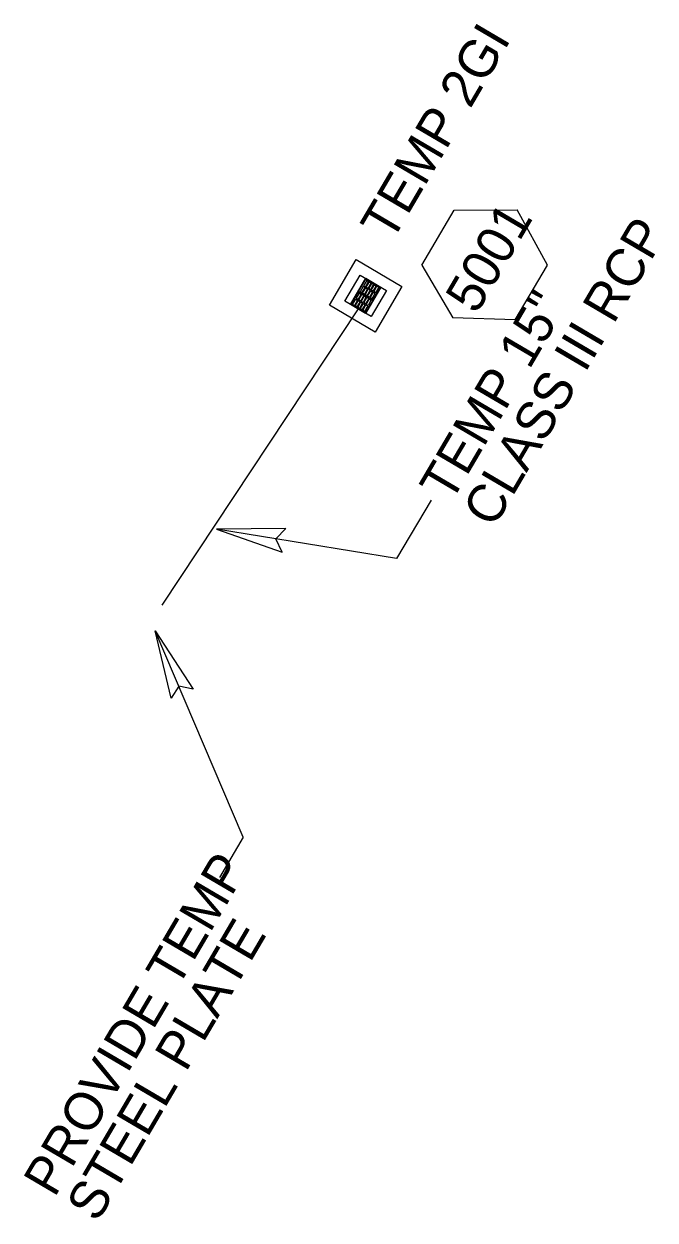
# Model space of a CAD drawing. Extents: x 2214978 to 2238755, y 984122 to 1016255.
# Drawn here: x 2229899 to 2229982.3, y 1001240.8 to 1001398.5 of the extents above; entities that cross this region are included whole.
import ezdxf

# ---------------------------------------------------------------- set-up
doc = ezdxf.new("R2010")
doc.units = 0
for name, color, linetype in [('Prop Drainage Structure Box Number Symbol CELL', 7, 'Continuous'), ('Prop Drainage Structure Drop Inlet Grate 2 Wide Slots and Sag Grates 840 22 CELL', 7, 'Continuous'), ('Prop Drainage Structure Drop Inlet Grate 2 Wide Slots and Sag Grates 840 22 Label', 7, 'Continuous'), ('Prop Drainage Structure Pipe RCP 15in Class III', 7, 'Continuous'), ('Prop Drainage Structure Plot Symbol 20 Scale', 7, 'Continuous'), ('Prop Drainage Structure Plot Symbol 50 Scale', 7, 'Continuous'), ('Prop Plan Preparation Drainage Notes Label', 7, 'Continuous')]:
    doc.layers.add(name, color=color, linetype=linetype)

msp = doc.modelspace()

# ---------------------------------------------------------------- linework, layer by layer
at = {"layer": 'Prop Drainage Structure Box Number Symbol CELL'}
for p, q in [((2229951.54, 1001366.72), (2229955.79, 1001373.96)), ((2229955.79, 1001373.96), (2229964.11, 1001374.02)), ((2229968.1, 1001366.73), (2229964.11, 1001374.02)), ((2229951.54, 1001366.72), (2229955.64, 1001359.76)), ((2229963.84, 1001359.49), (2229968.1, 1001366.73)), ((2229963.84, 1001359.49), (2229955.64, 1001359.76))]:
    msp.add_line(p, q, dxfattribs=at)
at = {"layer": 'Prop Drainage Structure Drop Inlet Grate 2 Wide Slots and Sag Grates 840 22 CELL'}
for p, q in [((2229945.13, 1001364.39), (2229945.13, 1001364.39)), ((2229943.11, 1001363.26), (2229943.11, 1001363.26)), ((2229944.12, 1001362.67), (2229944.12, 1001362.67)), ((2229943.11, 1001360.94), (2229943.11, 1001360.94)), ((2229945.13, 1001362.07), (2229945.13, 1001362.07))]:
    msp.add_line(p, q, dxfattribs=at)
for points in [[(2229942.1, 1001361.53), (2229944.13, 1001364.98), (2229946.14, 1001363.8), (2229944.11, 1001360.35), (2229942.1, 1001361.53)], [(2229942.19, 1001361.56), (2229944.15, 1001364.9), (2229946.05, 1001363.78), (2229944.09, 1001360.44), (2229942.19, 1001361.56)], [(2229943.18, 1001363.23), (2229944.15, 1001364.88), (2229946.04, 1001363.77), (2229945.07, 1001362.12), (2229943.18, 1001363.23)], [(2229943.62, 1001363.07), (2229944.04, 1001363.79), (2229943.81, 1001363.92), (2229943.39, 1001363.21), (2229943.62, 1001363.07)], [(2229944.08, 1001363.86), (2229944.51, 1001364.58), (2229944.27, 1001364.71), (2229943.85, 1001364), (2229944.08, 1001363.86)], [(2229944.18, 1001363.8), (2229944.61, 1001364.52), (2229944.84, 1001364.38), (2229944.42, 1001363.66), (2229944.18, 1001363.8)], [(2229944.52, 1001363.61), (2229944.94, 1001364.32), (2229945.17, 1001364.19), (2229944.75, 1001363.47), (2229944.52, 1001363.61)], [(2229944.85, 1001363.41), (2229945.27, 1001364.13), (2229945.5, 1001363.99), (2229945.08, 1001363.27), (2229944.85, 1001363.41)], [(2229945.18, 1001363.22), (2229945.6, 1001363.93), (2229945.84, 1001363.8), (2229945.41, 1001363.08), (2229945.18, 1001363.22)], [(2229942.2, 1001361.56), (2229943.17, 1001363.21), (2229945.06, 1001362.1), (2229944.09, 1001360.45), (2229942.2, 1001361.56)], [(2229942.4, 1001361.54), (2229942.83, 1001362.25), (2229943.06, 1001362.12), (2229942.64, 1001361.4), (2229942.4, 1001361.54)], [(2229942.87, 1001362.33), (2229943.29, 1001363.04), (2229943.52, 1001362.91), (2229943.1, 1001362.19), (2229942.87, 1001362.33)], [(2229943.2, 1001362.13), (2229943.62, 1001362.85), (2229943.86, 1001362.71), (2229943.43, 1001361.99), (2229943.2, 1001362.13)], [(2229943.53, 1001361.94), (2229943.96, 1001362.65), (2229944.19, 1001362.52), (2229943.77, 1001361.8), (2229943.53, 1001361.94)], [(2229943.72, 1001363.01), (2229944.14, 1001363.73), (2229944.37, 1001363.59), (2229943.95, 1001362.87), (2229943.72, 1001363.01)], [(2229943.87, 1001361.74), (2229944.29, 1001362.46), (2229944.52, 1001362.32), (2229944.1, 1001361.6), (2229943.87, 1001361.74)], [(2229944.05, 1001362.82), (2229944.47, 1001363.53), (2229944.71, 1001363.4), (2229944.28, 1001362.68), (2229944.05, 1001362.82)], [(2229944.2, 1001361.54), (2229944.62, 1001362.26), (2229944.85, 1001362.13), (2229944.43, 1001361.41), (2229944.2, 1001361.54)], [(2229944.38, 1001362.62), (2229944.81, 1001363.34), (2229945.04, 1001363.2), (2229944.62, 1001362.48), (2229944.38, 1001362.62)], [(2229944.72, 1001362.42), (2229945.14, 1001363.14), (2229945.37, 1001363.01), (2229944.95, 1001362.29), (2229944.72, 1001362.42)], [(2229942.74, 1001361.34), (2229943.16, 1001362.06), (2229943.39, 1001361.92), (2229942.97, 1001361.2), (2229942.74, 1001361.34)], [(2229943.07, 1001361.15), (2229943.49, 1001361.86), (2229943.72, 1001361.73), (2229943.3, 1001361.01), (2229943.07, 1001361.15)], [(2229943.4, 1001360.95), (2229943.82, 1001361.67), (2229944.06, 1001361.53), (2229943.63, 1001360.81), (2229943.4, 1001360.95)], [(2229943.73, 1001360.75), (2229944.16, 1001361.47), (2229944.39, 1001361.34), (2229943.97, 1001360.62), (2229943.73, 1001360.75)]]:
    msp.add_lwpolyline(points, dxfattribs=at)
at = {"layer": 'Prop Drainage Structure Pipe RCP 15in Class III'}
msp.add_line((2229943.11, 1001360.94), (2229917.21, 1001321.89), dxfattribs=at)
at = {"layer": 'Prop Drainage Structure Plot Symbol 20 Scale'}
msp.add_lwpolyline([(2229941.38, 1001361.96), (2229943.41, 1001365.4), (2229946.86, 1001363.38), (2229944.83, 1001359.93)], close=True, dxfattribs=at)
at = {"layer": 'Prop Drainage Structure Plot Symbol 50 Scale'}
msp.add_lwpolyline([(2229939.33, 1001361.42), (2229942.88, 1001367.46), (2229948.91, 1001363.91), (2229945.36, 1001357.88)], close=True, dxfattribs=at)
at = {"layer": 'Prop Plan Preparation Drainage Notes Label'}
for p, q in [((2229952.74, 1001335.73), (2229948.2, 1001328.01)), ((2229948.2, 1001328.01), (2229924.45, 1001331.91)), ((2229927.95, 1001291.28), (2229916.35, 1001318.47)), ((2229927.95, 1001291.28), (2229924.83, 1001285.96))]:
    msp.add_line(p, q, dxfattribs=at)
for points in [[(2229933.59, 1001331.98), (2229924.45, 1001331.91), (2229933.12, 1001328.86), (2229932.25, 1001330.63)], [(2229918.45, 1001309.59), (2229916.35, 1001318.47), (2229921.37, 1001310.78), (2229919.45, 1001311.21)]]:
    msp.add_lwpolyline(points, close=True, dxfattribs=at)

# ---------------------------------------------------------------- texts
at = {"layer": 'Prop Drainage Structure Box Number Symbol CELL'}
msp.add_text('5001', height=5, rotation=59.5521, dxfattribs=at).set_placement((2229958.73, 1001360.11))
at = {"layer": 'Prop Drainage Structure Drop Inlet Grate 2 Wide Slots and Sag Grates 840 22 Label'}
msp.add_text('TEMP 2GI', height=5, rotation=59.5521, dxfattribs=at).set_placement((2229947.55, 1001369.63))
at = {"layer": 'Prop Plan Preparation Drainage Notes Label'}
for s, p in [('CLASS III RCP', (2229961.01, 1001331.9)), ('TEMP 15"', (2229955.35, 1001335.22)), ('PROVIDE TEMP', (2229903.07, 1001243.64)), ('STEEL PLATE', (2229908.72, 1001240.32))]:
    msp.add_text(s, height=5, rotation=59.566, dxfattribs=at).set_placement(p)

doc.saveas('drawing.dxf')
